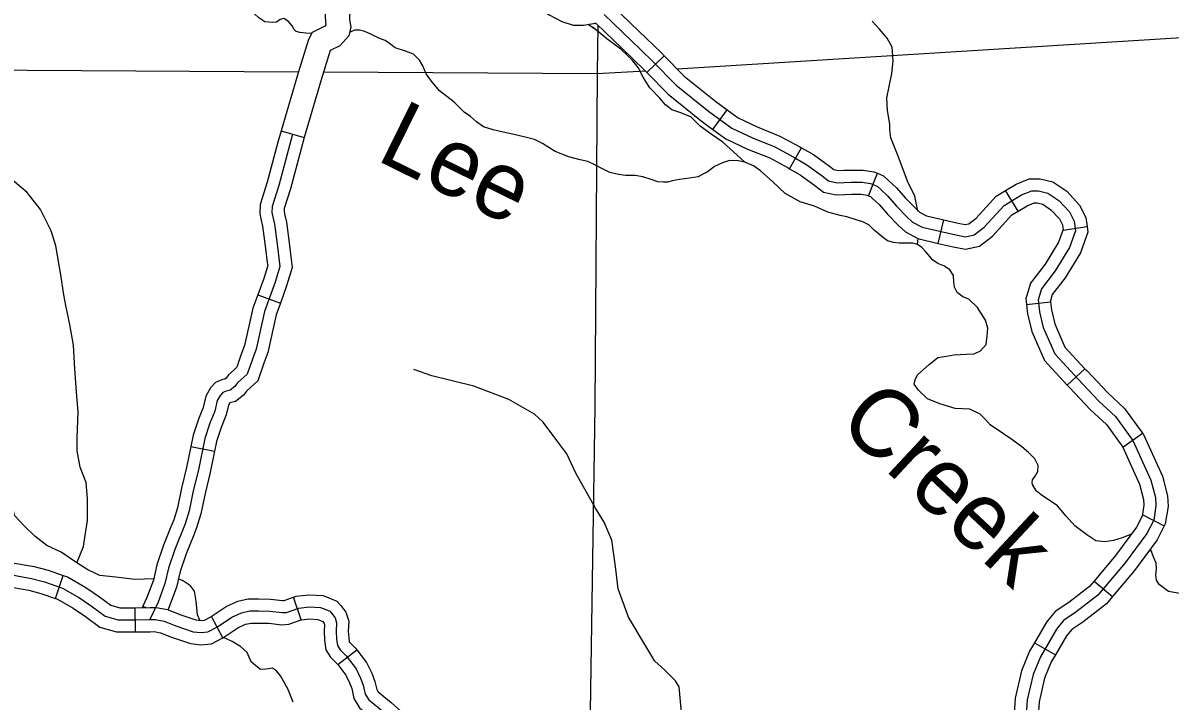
# Model space of a CAD drawing. Extents: x 22866 to 28196, y 1324810 to 1328105.
# Drawn here: x 25134.1 to 25304.9, y 1326185.2 to 1326286.2 of the extents above; entities that cross this region are included whole.
import ezdxf

# ---------------------------------------------------------------- set-up
doc = ezdxf.new("R2010")
doc.units = 0
for name, color, linetype in [('Level 10', 7, 'Continuous'), ('Level 31', 7, 'Continuous'), ('Level 32', 7, 'Continuous'), ('Level 35', 7, 'Continuous'), ('Level 45', 7, 'Continuous'), ('Level 46', 7, 'Continuous'), ('Level 5', 7, 'Continuous')]:
    doc.layers.add(name, color=color, linetype=linetype)

msp = doc.modelspace()

# ---------------------------------------------------------------- linework, layer by layer
at = {"layer": 'Level 10'}
for points in [[(25131.9, 1326204.1), (25135.4, 1326203.48), (25137.31, 1326202.97), (25139.99, 1326202.04), (25142.52, 1326200.6), (25144.48, 1326199.26), (25146.36, 1326197.86), (25148.28, 1326197.31), (25150.78, 1326197.31), (25153.01, 1326197.34), (25153.81, 1326197.36), (25155.12, 1326197.12), (25156.86, 1326196.4), (25159.47, 1326195.54), (25160.63, 1326195.4), (25161.66, 1326195.5), (25163.07, 1326196.26), (25165.23, 1326197.7), (25166.67, 1326198.35), (25167.87, 1326198.63), (25169.17, 1326198.63), (25170.85, 1326198.59), (25172.7, 1326198.39), (25173.34, 1326198.42), (25175.19, 1326199.07), (25176.74, 1326199.24), (25178.42, 1326199.14), (25179.2, 1326198.83), (25179.79, 1326198.59), (25180.06, 1326198.28), (25180.58, 1326197.6), (25180.82, 1326196.88), (25180.75, 1326195.61), (25180.82, 1326194.44), (25180.95, 1326193.48), (25181.33, 1326192.86), (25182.22, 1326191.97), (25183.73, 1326190.02), (25184.38, 1326188.64), (25184.79, 1326187.58)], [(25184.79, 1326187.58), (25185.09, 1326186.26), (25185.6, 1326185.4), (25187.75, 1326183.63), (25189.56, 1326182.02), (25191.56, 1326180.21), (25193.29, 1326178.96), (25195.91, 1326178.05), (25197.91, 1326177.67), (25202.97, 1326176.72), (25210.58, 1326174.4)]]:
    msp.add_lwpolyline(points, dxfattribs=at)
at = {"layer": 'Level 31'}
for points in [[(25220.66, 1326287.47), (25221.99, 1326286.2), (25224.56, 1326283.7), (25227.85, 1326280.54)], [(25227.85, 1326280.54), (25231.38, 1326276.95), (25236.18, 1326273.08), (25239.67, 1326270.54), (25242.74, 1326269.09)], [(25242.74, 1326269.09), (25246.06, 1326267.75), (25248.91, 1326266.21), (25250.83, 1326265.11), (25253.12, 1326263.46), (25254.08, 1326262.71), (25255.35, 1326262.43), (25256.41, 1326262.47), (25257.44, 1326262.5), (25259.09, 1326262.5), (25260.32, 1326262.3), (25261.28, 1326261.92), (25261.83, 1326261.4), (25262.89, 1326260.41), (25264.16, 1326258.93), (25265.74, 1326257.32), (25266.56, 1326256.57), (25268, 1326255.8)], [(25268, 1326255.8), (25273, 1326254.64), (25274.44, 1326254.36), (25275.74, 1326254.64), (25277.25, 1326255.8), (25280.2, 1326259.03), (25282.8, 1326260.6), (25284.31, 1326261.22), (25285.34, 1326261.22), (25286.71, 1326260.88), (25288.36, 1326259.78), (25289.93, 1326258.07), (25290.62, 1326256.69), (25290.82, 1326255.25), (25289.93, 1326252.78), (25287.81, 1326249.28), (25285.75, 1326246.61), (25285.27, 1326244.96), (25285.48, 1326243.18), (25286.02, 1326240.85), (25287.74, 1326236.93), (25291.23, 1326233.16), (25294.32, 1326229.87), (25296.79, 1326227.6), (25299.39, 1326224.03)], [(25299.39, 1326224.03), (25302.07, 1326218.13), (25302.75, 1326215.52), (25302.82, 1326214.29), (25302.48, 1326212.16), (25301.45, 1326210.17), (25298.23, 1326205.78), (25294.18, 1326200.98), (25290.89, 1326198.44), (25289.04, 1326197.2), (25288.01, 1326195.94), (25285.61, 1326191.82), (25284.52, 1326189.15), (25283.63, 1326185.37), (25283.21, 1326178.65), (25283.21, 1326172.82), (25283.78, 1326167.93)]]:
    msp.add_lwpolyline(points, dxfattribs=at)
at = {"layer": 'Level 32'}
for p, q in [((25227.02, 1326278.82), (25229.59, 1326281.34)), ((25236.84, 1326270.37), (25238.95, 1326273.29)), ((25248.24, 1326264.51), (25250.03, 1326267.64)), ((25260.03, 1326260.48), (25261.35, 1326263.83)), ((25282.29, 1326258.19), (25280.42, 1326261.27)), ((25270.4, 1326253.39), (25271.22, 1326256.9)), ((25288.99, 1326255.38), (25292.55, 1326255.89)), ((25283.54, 1326244.28), (25287.11, 1326244.69)), ((25289.6, 1326232.27), (25292.25, 1326234.72)), ((25297.9, 1326223.02), (25300.81, 1326225.14)), ((25300.86, 1326212.95), (25304.06, 1326211.29)), ((25138.94, 1326200.5), (25140.12, 1326203.9)), ((25293.61, 1326203.09), (25296.36, 1326200.77)), ((25175.56, 1326197.29), (25174.37, 1326200.69)), ((25150.87, 1326195.51), (25150.81, 1326199.11)), ((25163.87, 1326194.64), (25162.16, 1326197.82)), ((25284.74, 1326193.89), (25287.85, 1326192.08)), ((25180.98, 1326190.64), (25183.83, 1326192.84))]:
    msp.add_line(p, q, dxfattribs=at)
for points in [[(25206.76, 1326291.42), (25209.04, 1326290), (25212.45, 1326287.43), (25214.35, 1326286.42), (25216.04, 1326285.91), (25217.56, 1326285.91), (25219.05, 1326286.13), (25219.4, 1326286.24)], [(25221.16, 1326289.31), (25221.79, 1326288.88), (25223.24, 1326287.5), (25225.81, 1326284.99), (25229.12, 1326281.82), (25229.59, 1326281.34)], [(25219.31, 1326286.21), (25219.52, 1326286.07), (25220.74, 1326284.91), (25223.31, 1326282.4), (25226.59, 1326279.26), (25227.02, 1326278.82)], [(25229.59, 1326281.34), (25232.59, 1326278.29), (25237.27, 1326274.51), (25238.95, 1326273.29)], [(25227.02, 1326278.82), (25230.17, 1326275.62), (25235.08, 1326271.65), (25236.84, 1326270.37)], [(25238.95, 1326273.29), (25240.59, 1326272.1), (25243.46, 1326270.74), (25246.83, 1326269.38), (25249.78, 1326267.78), (25250.03, 1326267.64)], [(25236.84, 1326270.37), (25238.75, 1326268.98), (25242.02, 1326267.44), (25245.3, 1326266.12), (25248.03, 1326264.63), (25248.24, 1326264.51)], [(25174.27, 1326269.66), (25173.79, 1326267.96), (25172.21, 1326262.03), (25171.22, 1326258.87), (25171.18, 1326258.01), (25171.56, 1326256.26), (25172.01, 1326252.86), (25172.28, 1326250.77), (25172.38, 1326249.95), (25171.66, 1326247.61), (25170.09, 1326243.22), (25168.84, 1326237.65)], [(25250.03, 1326267.64), (25251.8, 1326266.63), (25254.21, 1326264.9), (25254.87, 1326264.38), (25255.52, 1326264.24), (25256.36, 1326264.27), (25257.41, 1326264.3), (25259.24, 1326264.3), (25260.8, 1326264.04), (25261.35, 1326263.83)], [(25248.24, 1326264.51), (25249.85, 1326263.59), (25252.04, 1326262.02), (25253.3, 1326261.04), (25255.19, 1326260.63), (25256.47, 1326260.67), (25257.47, 1326260.7), (25258.94, 1326260.7), (25259.84, 1326260.55), (25260.03, 1326260.48)], [(25261.35, 1326263.83), (25262.26, 1326263.47), (25263.06, 1326262.72), (25264.19, 1326261.66), (25265.49, 1326260.15), (25266.99, 1326258.62), (25267.61, 1326258.05), (25268.63, 1326257.5), (25271.22, 1326256.9)], [(25280.42, 1326261.27), (25281.99, 1326262.22), (25283.96, 1326263.02), (25285.56, 1326263.02), (25287.45, 1326262.55), (25289.53, 1326261.16), (25291.43, 1326259.1), (25292.36, 1326257.24), (25292.55, 1326255.89)], [(25271.22, 1326256.9), (25273.37, 1326256.4), (25274.42, 1326256.2), (25274.97, 1326256.31), (25276.03, 1326257.13), (25279.04, 1326260.43), (25280.42, 1326261.27)], [(25260.03, 1326260.48), (25260.3, 1326260.37), (25260.6, 1326260.09), (25261.59, 1326259.16), (25262.83, 1326257.72), (25264.48, 1326256.03), (25265.51, 1326255.09), (25267.36, 1326254.1), (25270.4, 1326253.39)], [(25270.4, 1326253.39), (25272.63, 1326252.87), (25274.46, 1326252.52), (25276.52, 1326252.96), (25278.47, 1326254.47), (25281.35, 1326257.62), (25282.29, 1326258.19)], [(25282.29, 1326258.19), (25283.62, 1326258.99), (25284.67, 1326259.42), (25285.12, 1326259.42), (25285.97, 1326259.21), (25287.18, 1326258.4), (25288.43, 1326257.03), (25288.88, 1326256.15), (25288.99, 1326255.38)], [(25288.98, 1326255.44), (25288.3, 1326253.56), (25286.32, 1326250.3), (25284.12, 1326247.44), (25283.44, 1326245.12), (25283.54, 1326244.28)], [(25292.55, 1326255.89), (25292.67, 1326255.06), (25291.56, 1326252), (25289.29, 1326248.27), (25287.38, 1326245.78), (25287.1, 1326244.81), (25287.11, 1326244.69)], [(25283.54, 1326244.28), (25283.7, 1326242.87), (25284.31, 1326240.27), (25286.21, 1326235.93), (25289.6, 1326232.27)], [(25287.11, 1326244.69), (25287.25, 1326243.49), (25287.74, 1326241.42), (25289.27, 1326237.94), (25292.25, 1326234.72)], [(25168.84, 1326237.65), (25168.27, 1326236.14), (25167.52, 1326233.91), (25166.08, 1326232.6), (25165.67, 1326232.06), (25164.98, 1326231.51), (25164.36, 1326231.37), (25163.85, 1326231.16), (25163.51, 1326230.79), (25163.03, 1326229.96), (25162.66, 1326228.38), (25161.94, 1326226.59), (25161.19, 1326224.33), (25160.23, 1326219.63), (25159.47, 1326216.54), (25158.86, 1326213.56), (25158.27, 1326211.63), (25156.73, 1326207.78), (25155.77, 1326205.01), (25155.26, 1326202.71), (25154.23, 1326199.93), (25153.01, 1326197.34)], [(25292.25, 1326234.72), (25292.55, 1326234.39), (25295.59, 1326231.15), (25298.14, 1326228.81), (25300.81, 1326225.14)], [(25289.6, 1326232.27), (25289.92, 1326231.93), (25293.05, 1326228.59), (25295.44, 1326226.4), (25297.9, 1326223.02)], [(25300.81, 1326225.14), (25300.96, 1326224.94), (25303.77, 1326218.73), (25304.54, 1326215.8), (25304.63, 1326214.19), (25304.21, 1326211.59), (25304.06, 1326211.29)], [(25297.83, 1326223.12), (25300.36, 1326217.52), (25300.96, 1326215.24), (25301.01, 1326214.38), (25300.74, 1326212.73), (25300.86, 1326212.95)], [(25300.86, 1326212.95), (25299.91, 1326211.12), (25296.81, 1326206.89), (25293.61, 1326203.09)], [(25304.06, 1326211.29), (25302.98, 1326209.22), (25299.64, 1326204.67), (25296.36, 1326200.77)], [(25127.62, 1326206.9), (25132.25, 1326205.87), (25135.79, 1326205.24), (25137.84, 1326204.69), (25140.12, 1326203.9)], [(25126.83, 1326203.39), (25131.55, 1326202.33), (25135, 1326201.72), (25136.79, 1326201.25), (25138.94, 1326200.5)], [(25140.12, 1326203.9), (25140.73, 1326203.69), (25143.48, 1326202.13), (25145.53, 1326200.73), (25147.18, 1326199.5), (25148.53, 1326199.11), (25150.77, 1326199.11), (25150.81, 1326199.11)], [(25293.61, 1326203.09), (25292.93, 1326202.28), (25289.84, 1326199.9), (25287.82, 1326198.55), (25286.53, 1326196.97), (25284.74, 1326193.89)], [(25138.94, 1326200.5), (25139.24, 1326200.39), (25141.57, 1326199.07), (25143.43, 1326197.8), (25145.55, 1326196.22), (25148.03, 1326195.51), (25150.8, 1326195.51), (25150.87, 1326195.51)], [(25162.14, 1326197.8), (25164.35, 1326199.28), (25166.09, 1326200.07), (25167.66, 1326200.43), (25169.19, 1326200.43), (25170.97, 1326200.39), (25172.75, 1326200.19), (25172.99, 1326200.2), (25174.37, 1326200.69)], [(25174.37, 1326200.69), (25174.79, 1326200.84), (25176.69, 1326201.05), (25178.81, 1326200.92), (25179.88, 1326200.5), (25180.86, 1326200.1), (25181.46, 1326199.42), (25182.19, 1326198.44), (25182.63, 1326197.12), (25182.55, 1326195.61), (25182.61, 1326194.62), (25182.68, 1326194.1), (25182.75, 1326193.98), (25183.58, 1326193.16), (25183.83, 1326192.84)], [(25296.36, 1326200.77), (25295.43, 1326199.67), (25291.94, 1326196.97), (25290.27, 1326195.86), (25289.5, 1326194.91), (25287.85, 1326192.08)], [(25150.81, 1326199.11), (25152.98, 1326199.14), (25153.96, 1326199.16), (25155.63, 1326198.85), (25157.49, 1326198.08), (25159.86, 1326197.3), (25160.65, 1326197.21), (25161.13, 1326197.26), (25162.16, 1326197.82)], [(25163.87, 1326194.64), (25164, 1326194.71), (25166.1, 1326196.12), (25167.24, 1326196.64), (25168.07, 1326196.82), (25169.15, 1326196.82), (25170.73, 1326196.79), (25172.65, 1326196.58), (25173.7, 1326196.64), (25175.56, 1326197.29)], [(25175.56, 1326197.29), (25175.6, 1326197.3), (25176.78, 1326197.44), (25178.02, 1326197.36), (25178.53, 1326197.16), (25178.71, 1326197.09), (25178.96, 1326196.75), (25179, 1326196.63), (25178.94, 1326195.6), (25179.02, 1326194.26), (25179.22, 1326192.86), (25179.9, 1326191.74), (25180.87, 1326190.78), (25180.98, 1326190.64)], [(25150.87, 1326195.51), (25153.04, 1326195.54), (25153.67, 1326195.55), (25154.6, 1326195.38), (25156.24, 1326194.71), (25159.08, 1326193.77), (25160.62, 1326193.59), (25162.2, 1326193.75), (25163.87, 1326194.64)], [(25284.74, 1326193.89), (25284, 1326192.62), (25282.8, 1326189.7), (25281.84, 1326185.64), (25281.55, 1326180.93)], [(25183.83, 1326192.84), (25185.27, 1326190.96), (25186.04, 1326189.35), (25186.52, 1326188.1), (25186.78, 1326186.93), (25186.98, 1326186.59), (25188.92, 1326185), (25190.76, 1326183.36), (25190.97, 1326183.17)], [(25287.85, 1326192.08), (25287.23, 1326191.03), (25286.24, 1326188.6), (25285.41, 1326185.11), (25285.14, 1326180.71)], [(25180.98, 1326190.64), (25182.19, 1326189.07), (25182.72, 1326187.93), (25183.06, 1326187.06), (25183.39, 1326185.59), (25184.21, 1326184.21), (25186.58, 1326182.26), (25188.36, 1326180.68), (25188.56, 1326180.5)]]:
    msp.add_lwpolyline(points, dxfattribs=at)
at = {"layer": 'Level 35'}
for points in [[(25176.24, 1326284.71), (25175.34, 1326284.81), (25174.79, 1326284.94), (25174.47, 1326285.23), (25174.21, 1326285.78), (25173.66, 1326286.46), (25172.98, 1326286.87), (25172.43, 1326286.72), (25171.86, 1326286.35), (25171.28, 1326286.3), (25170.11, 1326286.4), (25169.24, 1326287), (25168.57, 1326287.58), (25167.73, 1326287.89), (25166.84, 1326288), (25166.13, 1326287.87), (25165.43, 1326287.76), (25164.93, 1326287.89), (25164.3, 1326288.39), (25163.47, 1326289.15), (25162.08, 1326290.12), (25160.67, 1326291.22)], [(25193.67, 1326279.83), (25193.15, 1326280.7), (25192.24, 1326281.59), (25191.09, 1326282.01), (25189.52, 1326282.51), (25188.68, 1326283.16), (25188.03, 1326283.61), (25187.09, 1326283.95), (25186.02, 1326284.5), (25185.02, 1326284.94), (25184.21, 1326285.15), (25183.46, 1326285.15), (25182.75, 1326284.81)], [(25219.57, 1326285.11), (25218.26, 1326286.01)], [(25241.59, 1326265.48), (25239.92, 1326267.01), (25238.32, 1326268.47), (25236.6, 1326269.68), (25234.96, 1326270.86), (25233.54, 1326272.22), (25231.9, 1326272.9), (25230.72, 1326273.29), (25229.8, 1326274.04), (25228.94, 1326275.04), (25227.44, 1326276.54), (25226.48, 1326278.14), (25225.73, 1326279.57), (25224.91, 1326280.57), (25224.2, 1326281.32), (25223.16, 1326282.32), (25221.03, 1326283.86), (25219.57, 1326285.11), (25218.91, 1326285.59)], [(25267.35, 1326258.18), (25266.91, 1326260.43), (25265.84, 1326262.65), (25264.42, 1326266.39), (25263.35, 1326269.11), (25263.2, 1326270.28), (25263.17, 1326271.14), (25262.85, 1326273.19), (25262.74, 1326275.08), (25263.1, 1326276.75), (25263.49, 1326278.68), (25263.7, 1326280.59), (25263.56, 1326282.61), (25262.81, 1326283.96), (25261.67, 1326285.32), (25260.57, 1326286.5)], [(25177.12, 1326284.67), (25176.24, 1326284.71)], [(25206.99, 1326269.64), (25205.59, 1326269.97), (25204.15, 1326270.31), (25202.71, 1326270.75), (25201.62, 1326271.51), (25200.73, 1326272.27), (25199.81, 1326272.95), (25198.32, 1326274.41), (25196.13, 1326276.11), (25194.95, 1326277.53), (25194.17, 1326278.65), (25193.67, 1326279.83)], [(25139.77, 1326248.7), (25138.99, 1326253.01), (25138.31, 1326255.26), (25136.74, 1326258.45), (25134.76, 1326260.96), (25132.87, 1326262.58), (25131.72, 1326264.05), (25130.73, 1326265.62), (25129.27, 1326267.76), (25128.27, 1326269.59), (25127.18, 1326272.05)], [(25243.92, 1326264.2), (25242.9, 1326264.93), (25241.59, 1326265.48), (25240.6, 1326265.66), (25239.32, 1326265.71), (25238.27, 1326265.37), (25237.1, 1326264.82), (25236, 1326264.01), (25235.45, 1326263.73), (25234.64, 1326263.28), (25233.36, 1326263.1), (25231.89, 1326262.91), (25230.8, 1326262.68), (25230.14, 1326262.52), (25229.49, 1326262.52), (25228.63, 1326262.55), (25227.66, 1326262.89), (25226.42, 1326263.31), (25225.29, 1326263.52), (25223.83, 1326263.52), (25222.78, 1326263.65), (25221.48, 1326263.94), (25220.4, 1326264.51), (25219.25, 1326265.11), (25218.21, 1326265.56), (25217.08, 1326265.85), (25215.41, 1326266.29), (25213.35, 1326267.05), (25211.46, 1326268.25), (25210.29, 1326268.88), (25208.88, 1326269.19), (25206.99, 1326269.64)], [(25255.8, 1326257.52), (25253.95, 1326258.02), (25251.97, 1326258.91), (25249.82, 1326259.59), (25247.6, 1326260.8), (25245.75, 1326262.55), (25243.92, 1326264.2)], [(25270.36, 1326250.4), (25269.55, 1326250.92), (25269.13, 1326251.42), (25268.53, 1326252.15), (25267.96, 1326252.75), (25267.33, 1326253.2), (25266.62, 1326253.41), (25265.6, 1326253.43), (25264.58, 1326253.43), (25263.75, 1326253.54), (25262.86, 1326253.78), (25262.26, 1326254.19), (25260.87, 1326255.35), (25260.06, 1326256.13), (25259.17, 1326256.6), (25258.18, 1326256.89), (25256.77, 1326257.36), (25255.8, 1326257.52)], [(25267.33, 1326253.2), (25267.41, 1326254.09)], [(25279.98, 1326225.1), (25278.15, 1326226.38), (25277.37, 1326227.22), (25276.63, 1326227.95), (25275.12, 1326228.68), (25272.92, 1326228.79), (25270.62, 1326229.47), (25268.79, 1326230.25), (25267.48, 1326231.51), (25266.81, 1326232.4), (25266.96, 1326233.08), (25267.33, 1326233.81), (25269.05, 1326235.33), (25270.36, 1326236.38), (25271.61, 1326236.58), (25272.71, 1326236.79), (25274.59, 1326236.9), (25275.74, 1326236.95), (25276.69, 1326237.37), (25277.52, 1326238.31), (25277.68, 1326239.57), (25277.78, 1326240.77), (25277.42, 1326241.97), (25276.22, 1326243.86), (25274.96, 1326245.06), (25274.07, 1326245.43), (25273.24, 1326246.06), (25272.82, 1326246.84), (25272.71, 1326247.68), (25272.66, 1326248.62), (25272.14, 1326249.46), (25271.35, 1326249.98), (25270.36, 1326250.4)], [(25142.08, 1326231.29), (25141.81, 1326234.72), (25141.66, 1326238.23), (25141.08, 1326241.32), (25140.51, 1326244.14), (25140.19, 1326245.71), (25139.77, 1326248.7)], [(25222.75, 1326201.93), (25222.34, 1326205.24), (25221.81, 1326209.17), (25220.66, 1326211.84), (25219.36, 1326213.93), (25216.43, 1326219.16), (25215.07, 1326222.04), (25213.61, 1326224.03), (25211.57, 1326226.75), (25210.27, 1326227.94), (25206.45, 1326230.13), (25201.23, 1326232.12), (25195.01, 1326233.64), (25192.29, 1326234.58)], [(25142.15, 1326205.8), (25143.12, 1326208.22), (25143.38, 1326209.94), (25143.7, 1326212.09), (25143.7, 1326215.33), (25143.54, 1326217.79), (25142.65, 1326220.04), (25142.18, 1326222.5), (25142.18, 1326224.44), (25142.34, 1326228.26), (25142.08, 1326231.29)], [(25150.75, 1326203.31), (25147.96, 1326203.66), (25145.55, 1326203.92), (25143.77, 1326204.76), (25142.15, 1326205.8), (25139.8, 1326207.37), (25137.66, 1326208.37), (25135.88, 1326209.78), (25134.36, 1326211.25), (25132.9, 1326212.82), (25132.27, 1326215.38), (25131.28, 1326217.84), (25130.23, 1326220.09), (25128.3, 1326222.18), (25126.84, 1326223.39), (25125.42, 1326224.12), (25124.22, 1326225.48), (25123.39, 1326226.68), (25122.55, 1326227.78), (25121.14, 1326228.57), (25118.52, 1326229.3)], [(25288.18, 1326214.28), (25285.73, 1326215.94), (25285, 1326216.52), (25284.42, 1326217.46), (25284.37, 1326217.77), (25284.42, 1326218.14), (25284.84, 1326218.71), (25285.21, 1326219.39), (25285.26, 1326220.28), (25284.79, 1326221.28), (25283.85, 1326222.22), (25282.85, 1326223.06), (25281.34, 1326224.16), (25279.98, 1326225.1)], [(25299.16, 1326210.09), (25297.8, 1326209.52), (25296.49, 1326209.15), (25295.19, 1326208.94), (25293.88, 1326209.1), (25292.52, 1326209.99), (25290.74, 1326211.3), (25289.44, 1326212.76), (25288.18, 1326214.28)], [(25302.18, 1326207.44), (25301.94, 1326207.76)], [(25306.36, 1326201.21), (25304.69, 1326201.53), (25303.28, 1326202.58), (25302.91, 1326203.2), (25302.81, 1326203.94), (25302.91, 1326204.93), (25302.86, 1326205.77), (25302.5, 1326206.55), (25302.02, 1326207.9)], [(25153.57, 1326203.42), (25150.75, 1326203.31)], [(25160.45, 1326197.24), (25160.08, 1326198.07), (25159.9, 1326200.07), (25159.64, 1326201.58), (25159.06, 1326202.38), (25157.86, 1326203.18), (25157.25, 1326203.35)], [(25230.58, 1326170.3), (25230.86, 1326171.39), (25231.9, 1326176.57), (25232.11, 1326180.45), (25232.16, 1326183.53), (25231.8, 1326187.35), (25231.27, 1326188.22), (25229.65, 1326189.84), (25228.19, 1326191.15), (25226.99, 1326193.14), (25224.27, 1326197.69), (25222.75, 1326201.93)], [(25168.11, 1326191.07), (25167.5, 1326192.42), (25166.52, 1326193.35), (25165.24, 1326194.06), (25163.95, 1326194.68)], [(25174.33, 1326185.02), (25173.53, 1326187.02), (25172.47, 1326188.98), (25171.85, 1326189.73), (25171.27, 1326190.09), (25170.29, 1326189.95), (25169.49, 1326189.91), (25168.78, 1326190.44), (25168.11, 1326191.07), (25167.98, 1326191.33)]]:
    msp.add_lwpolyline(points, dxfattribs=at)
at = {"layer": 'Level 45'}
for p, q in [((25172.54, 1326270.15), (25176, 1326269.18)), ((25169.07, 1326245.71), (25172.46, 1326244.49)), ((25159.11, 1326223.14), (25162.63, 1326222.42)), ((25151.96, 1326199.34), (25152.41, 1326199.13))]:
    msp.add_line(p, q, dxfattribs=at)
for points in [[(25172.54, 1326270.15), (25172.05, 1326268.44), (25170.48, 1326262.53), (25169.43, 1326259.18), (25169.38, 1326257.86), (25169.55, 1326257.05)], [(25176, 1326269.18), (25175.53, 1326267.49), (25173.94, 1326261.53), (25173.01, 1326258.56), (25172.99, 1326258.17), (25173.07, 1326257.81)], [(25173.07, 1326257.81), (25173.34, 1326256.56), (25173.79, 1326253.09), (25174.07, 1326251), (25174.22, 1326249.78), (25173.37, 1326247.04), (25172.46, 1326244.49)], [(25169.55, 1326257.05), (25169.79, 1326255.95), (25170.22, 1326252.63), (25170.49, 1326250.54), (25170.55, 1326250.11), (25169.96, 1326248.18), (25169.07, 1326245.71)], [(25169.07, 1326245.71), (25168.35, 1326243.72), (25167.11, 1326238.16), (25166.57, 1326236.74), (25165.96, 1326234.93), (25165.57, 1326234.57)], [(25172.46, 1326244.49), (25171.82, 1326242.72), (25170.56, 1326237.13), (25169.97, 1326235.53), (25169.07, 1326232.89), (25167.98, 1326231.9)], [(25165.57, 1326234.57), (25164.74, 1326233.82), (25164.36, 1326233.32), (25164.18, 1326233.17), (25163.83, 1326233.09), (25162.8, 1326232.68), (25162.05, 1326231.86), (25161.33, 1326230.63), (25160.94, 1326228.92), (25160.25, 1326227.22), (25159.44, 1326224.8), (25159.11, 1326223.14)], [(25167.98, 1326231.9), (25167.41, 1326231.39), (25166.97, 1326230.79), (25165.78, 1326229.84), (25164.93, 1326229.65), (25164.72, 1326229.29), (25164.38, 1326227.83), (25163.63, 1326225.97), (25162.93, 1326223.86), (25162.63, 1326222.42)], [(25159.11, 1326223.14), (25158.47, 1326220.02), (25157.72, 1326216.94), (25157.11, 1326214), (25156.57, 1326212.22), (25156.15, 1326211.17)], [(25162.63, 1326222.42), (25161.98, 1326219.24), (25161.23, 1326216.15), (25160.6, 1326213.12), (25159.97, 1326211.03), (25159.49, 1326209.83)], [(25156.15, 1326211.17), (25155.04, 1326208.41), (25154.04, 1326205.5), (25153.53, 1326203.22), (25152.57, 1326200.63), (25151.96, 1326199.34)], [(25159.49, 1326209.83), (25158.42, 1326207.16), (25157.51, 1326204.51), (25156.99, 1326202.2), (25155.89, 1326199.23), (25155.7, 1326198.82)], [(25151.96, 1326199.34), (25151.86, 1326199.12)]]:
    msp.add_lwpolyline(points, dxfattribs=at)
at = {"layer": 'Level 46'}
for points in [[(25180.58, 1326292.11), (25180.43, 1326290.82), (25179.68, 1326289.37), (25179.06, 1326288.07), (25179.16, 1326286.39), (25179.23, 1326285.92), (25179.06, 1326285.74), (25177.18, 1326284.78)], [(25184.21, 1326292.18), (25183.94, 1326289.75), (25182.9, 1326287.76), (25182.71, 1326287.35), (25182.74, 1326286.76), (25182.92, 1326285.59), (25182.64, 1326284.31), (25181.27, 1326282.82), (25179.87, 1326282.11)], [(25177.18, 1326284.78), (25176.61, 1326283.77), (25175.08, 1326278.81), (25172.54, 1326270.17)], [(25179.87, 1326282.11), (25178.53, 1326277.77), (25176, 1326269.16)]]:
    msp.add_lwpolyline(points, dxfattribs=at)
at = {"layer": 'Level 5'}
for points in [[(25219.72, 1326285.88), (25219.62, 1326278.67)], [(25231.5, 1326279.4), (25340.23, 1326286.12)], [(25094.3, 1326279.44), (25175.12, 1326278.94)], [(25178.88, 1326278.92), (25219.62, 1326278.67)], [(25219.62, 1326278.67), (25219.28, 1326229.03), (25218.59, 1326183.67), (25218.27, 1326174.1)], [(25219.62, 1326278.67), (25226.75, 1326279.11)]]:
    msp.add_lwpolyline(points, dxfattribs=at)

# ---------------------------------------------------------------- texts
at = {"layer": 'Level 35'}
for s, rotation, p in [('Lee', 333.7559, (25186.5, 1326265.9)), ('Creek', 316.9136, (25255.16, 1326226.41))]:
    msp.add_text(s, height=10.139, rotation=rotation, dxfattribs=at).set_placement(p)

doc.saveas('drawing.dxf')
